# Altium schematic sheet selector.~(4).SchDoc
size A4
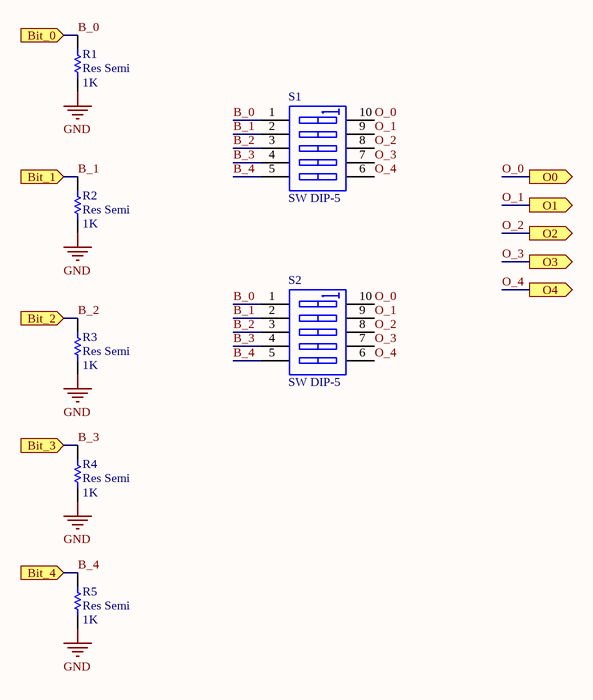
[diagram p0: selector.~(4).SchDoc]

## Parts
R1  Res Semi  value 1K  [2012[0805]]
R2  Res Semi  value 1K  [2012[0805]]
R3  Res Semi  value 1K  [2012[0805]]
R4  Res Semi  value 1K  [2012[0805]]
R5  Res Semi  value 1K  [2012[0805]]
S1  SW DIP-5  [N10A]
S2  SW DIP-5  [N10A]

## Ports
Bit_0 (in), Bit_1 (in), Bit_2 (in), Bit_3 (in), Bit_4 (in), O0 (out), O1 (out), O2 (out), O3 (out), O4 (out)

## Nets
GND: R1.1 R2.1 R3.1 R4.1 R5.1
B_0: R1.2 S1.1(A1) S2.1(A1) ; port Bit_0
B_1: R2.2 S1.2(A2) S2.2(A2) ; port Bit_1
B_2: R3.2 S1.3(A3) S2.3(A3) ; port Bit_2
B_3: R4.2 S1.4(A4) S2.4(A4) ; port Bit_3
B_4: R5.2 S1.5(A5) S2.5(A5) ; port Bit_4
O_0: S1.10(B1) S2.10(B1) ; port O0
O_1: S1.9(B2) S2.9(B2) ; port O1
O_2: S1.8(B3) S2.8(B3) ; port O2
O_3: S1.7(B4) S2.7(B4) ; port O3
O_4: S1.6(B5) S2.6(B5) ; port O4

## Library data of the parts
R1-R5 = Res Semi: Semiconductor Resistor
S1 S2 = SW DIP-5: DIP Switch, 5 Position, SPST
